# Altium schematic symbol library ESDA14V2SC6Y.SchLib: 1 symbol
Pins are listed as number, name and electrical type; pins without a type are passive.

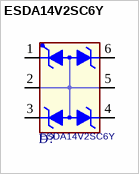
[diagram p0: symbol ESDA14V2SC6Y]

## ESDA14V2SC6Y
designator D?
footprint ST_SOT23-6L
pins: 1, 2, 3, 4, 5, 6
